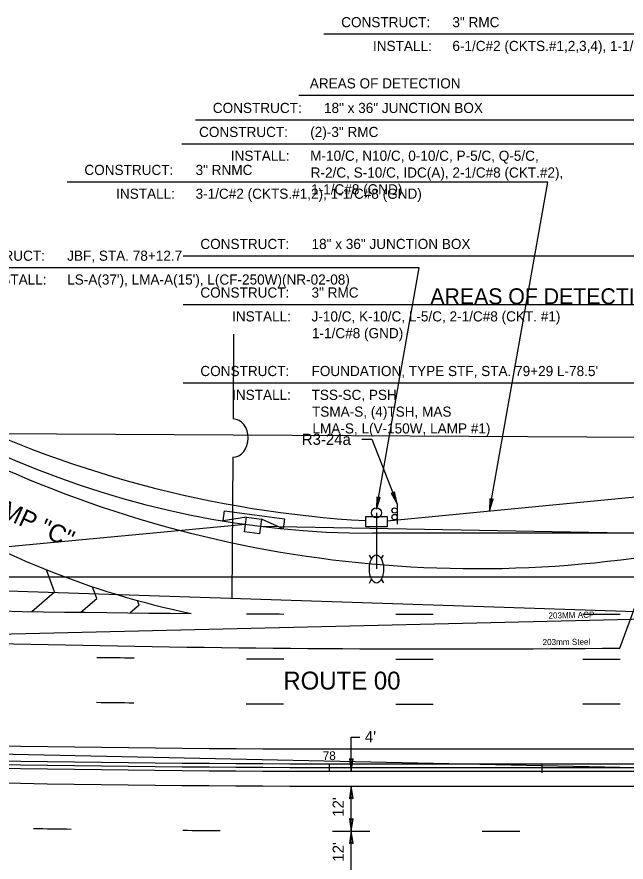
# Model space of a CAD drawing. Extents: x 488740 to 507913, y 466518 to 497949.
# Drawn here: x 503231.3 to 503394.3, y 496045.1 to 496271.3 of the extents above; entities that cross this region are included whole.
import ezdxf

# ---------------------------------------------------------------- set-up
doc = ezdxf.new("R2010")
doc.units = 0
for name, color, linetype in [('1', 7, 'Continuous'), ('10', 7, 'Continuous'), ('12', 7, 'Continuous'), ('23', 7, 'Continuous'), ('32', 7, 'Continuous'), ('34', 7, 'Continuous'), ('36', 7, 'Continuous'), ('38', 7, 'Continuous'), ('42', 7, 'Continuous'), ('6', 7, 'Continuous'), ('8', 7, 'Continuous')]:
    doc.layers.add(name, color=color, linetype=linetype)

msp = doc.modelspace()

# ---------------------------------------------------------------- linework, layer by layer
at = {"layer": '1'}
for p, q in [((503286.47, 496136.45), (503286.83, 496139.08)), ((503292.73, 496137.45), (503286.47, 496136.45)), ((503286.83, 496139.08), (503302.89, 496136.94)), ((503302.54, 496134.3), (503296.7, 496136.92)), ((503302.89, 496136.94), (503302.54, 496134.3)), ((503424.49, 496133.12), (503326.5, 496133.12)), ((503314.85, 496071.43), (503314.85, 496069.42)), ((503325.93, 496071.42), (503430.44, 496071.42)), ((503325.93, 496070.42), (503748.62, 496070.42)), ((503325.93, 496069.41), (503430.44, 496069.41))]:
    msp.add_line(p, q, dxfattribs=at)
msp.add_lwpolyline([(503292.2, 496133.48), (503292.73, 496137.45), (503296.7, 496136.92), (503296.17, 496132.96)], close=True, dxfattribs=at)
msp.add_lwpolyline([(503371.8, 496071.43), (503371.8, 496068.99)], dxfattribs=at)
for centre, radius, start, end in [((503326.5, 496378.08), 244.96, 224.0248, 270), ((503325.29, 501769.95), 5700.54, 267.68896, 270.0064), ((503325.29, 501769.95), 5699.54, 267.68896, 270.0064), ((503325.29, 501769.95), 5698.54, 267.68896, 270.0064)]:
    msp.add_arc(centre, radius, start, end, dxfattribs=at)
at = {"layer": '10'}
for p, q in [((503404.04, 496250.25), (503306.75, 496250.25)), ((503404.04, 496237.25), (503275.42, 496237.25)), ((503404.4, 496207.28), (503275.77, 496207.28)), ((503404.4, 496194.28), (503275.77, 496194.28)), ((503404.4, 496173.28), (503275.77, 496173.28))]:
    msp.add_line(p, q, dxfattribs=at)
at = {"layer": '12'}
for p, q in [((503442.09, 496266.63), (503313.47, 496266.63)), ((503407.72, 496243.68), (503279.1, 496243.68)), ((503373.35, 496227.09), (503244.73, 496227.09)), ((503357.73, 496139.11), (503373.35, 496227.09)), ((503338.98, 496204.14), (503210.36, 496204.14)), ((503327.51, 496139.52), (503338.98, 496204.14))]:
    msp.add_line(p, q, dxfattribs=at)
for points in [[(503327.51, 496139.52), (503328.55, 496142.69), (503328.02, 496142.43), (503327.62, 496142.86)], [(503357.73, 496139.11), (503358.77, 496142.28), (503358.24, 496142.02), (503357.84, 496142.45)]]:
    msp.add_lwpolyline(points, close=True, dxfattribs=at)
at = {"layer": '23'}
for p, q in [((503289.29, 496186.43), (503289.14, 496163.7)), ((503154.57, 496160.23), (503464.98, 496158.49)), ((503289.07, 496153.48), (503288.82, 496115.75)), ((503205.52, 496127.43), (503292.46, 496135.53)), ((503296.46, 496134.99), (503398.98, 496133.13)), ((503161.5, 496119.92), (503456.86, 496110.24)), ((503392.63, 496102.4), (503398.25, 496117.66)), ((503402.79, 496110.21), (503218.58, 496105.81)), ((503093.84, 496076.95), (503396.82, 496070.42))]:
    msp.add_line(p, q, dxfattribs=at)
msp.add_arc((503345.18, 500785.59), 4683.43, 266.95051, 270.58054, dxfattribs=at)
msp.add_ellipse((503289.11, 496158.59), major_axis=(0.03, 5.11), ratio=0.798047, start_param=3.141593, end_param=6.283185, dxfattribs=at)
at = {"layer": '32'}
msp.add_circle((503327.51, 496138.58), 1.34, dxfattribs=at)
at = {"layer": '36'}
for p, q in [((503241.34, 496117.48), (503239.18, 496123.34)), ((503235.26, 496112.18), (503241.34, 496117.48)), ((503252.66, 496115.68), (503251.51, 496118.8)), ((503248.41, 496111.98), (503252.66, 496115.68)), ((503263.97, 496113.88), (503263.51, 496115.13)), ((503263.97, 496113.88), (503261.61, 496111.82)), ((503332.68, 496111.46), (503342.7, 496111.46)), ((503382.76, 496111.47), (503392.78, 496111.47)), ((503332.68, 496099.44), (503342.7, 496099.44)), ((503382.76, 496099.45), (503392.78, 496099.45)), ((503332.69, 496087.42), (503342.7, 496087.42)), ((503382.76, 496087.43), (503392.78, 496087.43)), ((503325.93, 496075.4), (503432.85, 496075.41)), ((503325.93, 496065.44), (503444.2, 496065.44)), ((503315.77, 496053.41), (503325.78, 496053.41)), ((503355.83, 496053.42), (503365.85, 496053.42))]:
    msp.add_line(p, q, dxfattribs=at)
for centre, radius, start, end in [((503354.42, 496437.19), 313.54, 243.5604, 284.8261), ((503324.13, 496334.95), 228.02, 237.5021, 258.3112), ((503325.29, 501769.95), 5658.49, 267.68896, 269.52043), ((503325.29, 501769.95), 5658.49, 269.67047, 269.77188), ((503325.29, 501769.95), 5670.51, 269.26586, 269.36707), ((503325.29, 501769.95), 5670.51, 269.67068, 269.77188), ((503325.29, 501769.95), 5682.53, 269.26693, 269.36793), ((503325.29, 501769.95), 5682.53, 269.67089, 269.77188), ((503325.29, 501769.95), 5694.55, 267.68896, 270.00648), ((503325.29, 501769.95), 5704.51, 267.68892, 270.00638), ((503325.29, 501769.95), 5716.53, 269.10245, 269.20284), ((503325.29, 501769.95), 5716.53, 269.50296, 269.60336)]:
    msp.add_arc(centre, radius, start, end, dxfattribs=at)
at = {"layer": '38'}
for p, q in [((503320.78, 496069.44), (503320.78, 496078.55)), ((503320.78, 496078.55), (503323.06, 496078.55)), ((503320.78, 496053.41), (503320.78, 496065.44)), ((503320.78, 496041.39), (503320.78, 496053.41))]:
    msp.add_line(p, q, dxfattribs=at)
for points in [[(503320.78, 496069.44), (503321.25, 496072.74), (503320.78, 496072.39), (503320.3, 496072.74)], [(503320.78, 496065.44), (503320.3, 496062.14), (503320.78, 496062.49), (503321.25, 496062.14)], [(503320.78, 496053.41), (503321.25, 496056.72), (503320.78, 496056.36), (503320.3, 496056.72)], [(503320.78, 496053.41), (503320.3, 496050.1), (503320.78, 496050.46), (503321.25, 496050.1)]]:
    msp.add_lwpolyline(points, close=True, dxfattribs=at)
at = {"layer": '42'}
for p, q in [((503323.56, 496158.27), (503326.27, 496158.27)), ((503326.27, 496158.27), (503333.07, 496140.98)), ((503333.07, 496140.98), (503333.07, 496137.31)), ((503333.09, 496139.2), (503333.09, 496135.54))]:
    msp.add_line(p, q, dxfattribs=at)
msp.add_lwpolyline([(503333.07, 496140.98), (503332.3, 496144.23), (503331.99, 496143.72), (503331.42, 496143.88)], close=True, dxfattribs=at)
for centre in [(503332.37, 496139.2), (503332.38, 496137.43)]:
    msp.add_circle(centre, 0.721, dxfattribs=at)
at = {"layer": '6'}
for p, q in [((503330.34, 496136.47), (503418.04, 496144.91)), ((503405.68, 496121.4), (503174.52, 496121.4))]:
    msp.add_line(p, q, dxfattribs=at)
msp.add_lwpolyline([(503330.34, 496134.8), (503324.67, 496134.8), (503324.67, 496137.63), (503330.34, 496137.63)], close=True, dxfattribs=at)
msp.add_arc((503341.48, 496433.35), 297.34, 243.2081, 266.7595, dxfattribs=at)
at = {"layer": '8'}
for p, q in [((503327.51, 496138.58), (503327.51, 496123.55)), ((503325.59, 496127.26), (503326.17, 496126.22)), ((503328.81, 496126.26), (503329.37, 496127.26)), ((503325.62, 496119.77), (503326.21, 496120.83)), ((503328.81, 496120.82), (503329.37, 496119.82))]:
    msp.add_line(p, q, dxfattribs=at)
msp.add_ellipse((503327.51, 496123.55), major_axis=(0.02, -3.75), ratio=0.505309, dxfattribs=at)

# ---------------------------------------------------------------- texts
at = {"layer": '1'}
for s, height, rotation, p in [('RAMP "C"', 4.796, 334.9937, (503218.48, 496141.47)), ('78', 2.344, 359.895, (503313.14, 496072.43))]:
    msp.add_text(s, height=height, rotation=rotation, dxfattribs=at).set_placement(p)
msp.add_text('ROUTE 00', height=4.796, dxfattribs=at).set_placement((503302.59, 496091.29))
at = {"layer": '10'}
for s, height, p in [('AREAS OF DETECTION                      ', 2.7163, (503309.67, 496252.14)), ('CONSTRUCT:', 2.716, (503280.03, 496239.14)), ('(2)-3" RMC                              ', 2.7163, (503309.79, 496239.14)), ('INSTALL:', 2.716, (503288.53, 496232.77)), ('M-10/C, N10/C, 0-10/C, P-5/C, Q-5/C,    ', 2.7163, (503309.79, 496232.77)), ('R-2/C, S-10/C, IDC(A), 2-1/C#8 (CKT.#2), ', 2.7163, (503309.91, 496228.28)), ('1-1/C#8 (GND)                           ', 2.7163, (503310.03, 496223.79)), ('CONSTRUCT:', 2.716, (503280.38, 496209.17)), ('18" x 36" JUNCTION BOX                  ', 2.7163, (503310.14, 496209.17)), ('CONSTRUCT:', 2.716, (503280.38, 496196.17)), ('3" RMC                                  ', 2.7163, (503310.14, 496196.17)), ('INSTALL:', 2.716, (503288.88, 496189.79)), ('J-10/C, K-10/C, L-5/C, 2-1/C#8 (CKT. #1)', 2.7163, (503310.14, 496189.79)), ('1-1/C#8 (GND)                           ', 2.7163, (503310.26, 496185.3)), ('CONSTRUCT:', 2.716, (503280.38, 496175.17)), ("FOUNDATION, TYPE STF, STA. 79+29 L-78.5'", 2.7163, (503310.14, 496175.17)), ('INSTALL:', 2.716, (503288.88, 496168.79)), ('TSS-SC, PSH                             ', 2.7163, (503310.14, 496168.79)), ('TSMA-S, (4)TSH, MAS                     ', 2.7163, (503310.26, 496164.3)), ('LMA-S, L(V-150W, LAMP #1)               ', 2.7163, (503310.38, 496159.81))]:
    msp.add_text(s, height=height, dxfattribs=at).set_placement(p)
at = {"layer": '12'}
for s, height, p in [('CONSTRUCT:', 2.716, (503318.08, 496268.52)), ('3" RMC                             ', 2.7163, (503347.84, 496268.52)), ('INSTALL:', 2.716, (503326.58, 496262.15)), ('6-1/C#2 (CKTS.#1,2,3,4), 1-1/C#8 (GND)         ', 2.7163, (503347.84, 496262.15)), ('CONSTRUCT:', 2.716, (503283.71, 496245.57)), ('18" x 36" JUNCTION BOX             ', 2.7163, (503313.47, 496245.57)), ('CONSTRUCT:', 2.716, (503249.34, 496228.98)), ('3" RNMC                            ', 2.7163, (503279.1, 496228.98)), ('INSTALL:', 2.716, (503257.84, 496222.61)), ('3-1/C#2 (CKTS.#1,2), 1-1/C#8 (GND)             ', 2.7163, (503279.1, 496222.61)), ('CONSTRUCT:', 2.716, (503214.97, 496206.03)), ('JBF, STA. 78+12.7                  ', 2.7163, (503244.73, 496206.03)), ('INSTALL:', 2.716, (503223.47, 496199.65)), ("LS-A(37'), LMA-A(15'), L(CF-250W)(NR-02-08)      ", 2.7163, (503244.73, 496199.65))]:
    msp.add_text(s, height=height, dxfattribs=at).set_placement(p)
at = {"layer": '23'}
for s, height, rotation, p in [('203MM ACP', 1.62, 1.2275, (503373.58, 496110.28)), ('203mm Steel', 1.6205, 0.4405, (503371.99, 496103.18))]:
    msp.add_text(s, height=height, rotation=rotation, dxfattribs=at).set_placement(p)
at = {"layer": '34'}
msp.add_text('AREAS OF DETECTION', height=4.2548, dxfattribs=at).set_placement((503341.94, 496194.4))
at = {"layer": '38'}
for s, rotation, p in [("4'", 0.0065, (503324.41, 496077.21)), ("12'", 90, (503318.77, 496057.25)), ("12'", 90, (503318.77, 496045.24))]:
    msp.add_text(s, height=2.993, rotation=rotation, dxfattribs=at).set_placement(p)
at = {"layer": '42'}
msp.add_text('R3-24a', height=2.993, dxfattribs=at).set_placement((503307.53, 496156.77))

doc.saveas('drawing.dxf')
